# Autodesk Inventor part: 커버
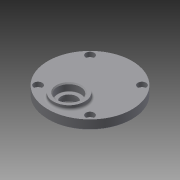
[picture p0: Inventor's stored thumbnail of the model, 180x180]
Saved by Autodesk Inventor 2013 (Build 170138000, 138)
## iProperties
Created: 2015-07
Part Number: 커버
Material: 일반
Document SubType Name: Modeling
Designer: user
Density: 1 g/cm^3
Author: user
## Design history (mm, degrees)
sketch "스케치1"
  geometry: C1 r 40 at (0, 0); 1 further point
  constraints: 1 centre point, 1 coincident
  dimensions: "d0" = 80 diameter of C1
extrude "돌출1" new body sketch "스케치1" distance "d1" = 9; taper "d2" = 0 deg
sketch "스케치2"
  geometry: L1 (0, 0)-(0, -20); C1 r 40 at (0, 0) reference; C2 r 15 at (0, -20)
  constraints: 2 end point, 1 centre point, 1 coincident, 1 vertical
  dimensions: "d3" = 20 distance of L1.start L1.end; "d4" = 30 diameter of C2
extrude "돌출2" join sketch "스케치2" distance "d5" = 4; taper "d6" = 0 deg
sketch "스케치3"
  geometry: L1 (0, 0)-(0, 11); L2 (0, 0)-(0, -20); C1 r 40 at (0, 0) reference; C2 r 14 at (0, 11); C3 r 14 at (0, -20)
  constraints: 4 end point, 2 centre point, 2 coincident, 1 collinear, 1 vertical
  dimensions: "d7" = 11 distance of L1.start L1.end; "d8" = 20 distance of L1.start L2.end; "d9" = 28 diameter of C2; "d10" = 28 diameter of C3
extrude "돌출3" join sketch "스케치3" distance "d11" = 3; taper "d12" = 0 deg
sketch "스케치4"
  geometry: C1 r 14 at (0, 0) reference; C2 r 11 at (0, 0); 1 further point
  constraints: 1 centre point, 1 coincident
  dimensions: "d13" = 22 diameter of C2
extrude "돌출4" cut sketch "스케치4" distance "d14" = 7; taper "d15" = 0 deg
sketch "스케치5"
  geometry: C1 r 9 at (0, 0); 2 further points
  constraints: 1 centre point, 1 coincident, 1 vertical alignment
  dimensions: "d16" = 18 diameter of C1
extrude "돌출5" cut sketch "스케치5" distance "d17" = 1; taper "d18" = 0 deg
sketch "스케치6"
  geometry: C1 r 14 at (0, 0) reference; C2 r 11 at (0, 0); 1 further point
  constraints: 1 centre point, 1 coincident
  dimensions: "d19" = 22 diameter of C2
extrude "돌출6" cut sketch "스케치6" distance "d20" = 7; taper "d21" = 0 deg
sketch "스케치7"
  geometry: C1 r 11 at (0, 0) reference; C2 r 7.5 at (0, 0); 1 further point
  constraints: 1 centre point, 1 coincident
  dimensions: "d22" = 15 diameter of C2
extrude "돌출7" cut sketch "스케치7" distance "d23" = 2; taper "d24" = 0 deg
sketch "스케치8"
  geometry: C1 r 15 at (0, 0) reference; C2 r 11 at (0, 0); 1 further point
  constraints: 1 centre point, 1 coincident
  dimensions: "d25" = 22 diameter of C2
extrude "돌출8" cut sketch "스케치8" distance "d26" = 7; taper "d27" = 0 deg
fillet "모깎기1" dims "d28" = 0.3
fillet "모깎기2" dims "d29" = 2
chamfer "모따기1" distance "d30" = 1; stored, may be unused: second distance "d31" = 2, angle "d32" = 45 deg
chamfer "모따기2" distance "d33" = 1; stored, may be unused: second distance "d34" = 2, angle "d35" = 45 deg
sketch "스케치9" dims "d36" = 70
  geometry: L1 (0, 0)-(-24.749, 24.749); L2 (0, 0)-(35, 0); C1 r 40 at (0, 0) reference; C2 r 4 at (-24.749, 24.749)
  constraints: 4 end point, 2 coincident, 1 centre point, 1 equal length, 1 horizontal, 3 other
  dimensions: "d37" = 135 deg angle of L2 L1; "d38" = 8 diameter of C2
extrude "돌출9" cut sketch "스케치9" distance "d39" = 4.4; taper "d40" = 0 deg
sketch "스케치10"
  geometry: C1 r 4 at (0, 0) reference; C2 r 2.25 at (0, 0); 1 further point
  constraints: 1 centre point, 1 coincident
  dimensions: "d44" = 4.5 diameter of C2
extrude "돌출10" cut sketch "스케치10" distance "d45" = 40; taper "d46" = 0 deg
node "솔리드1"
pattern_circular "원형 패턴1" dims angle "d42" = 360 deg
pattern_circular "원형 패턴2" dims angle "d48" = 360 deg
